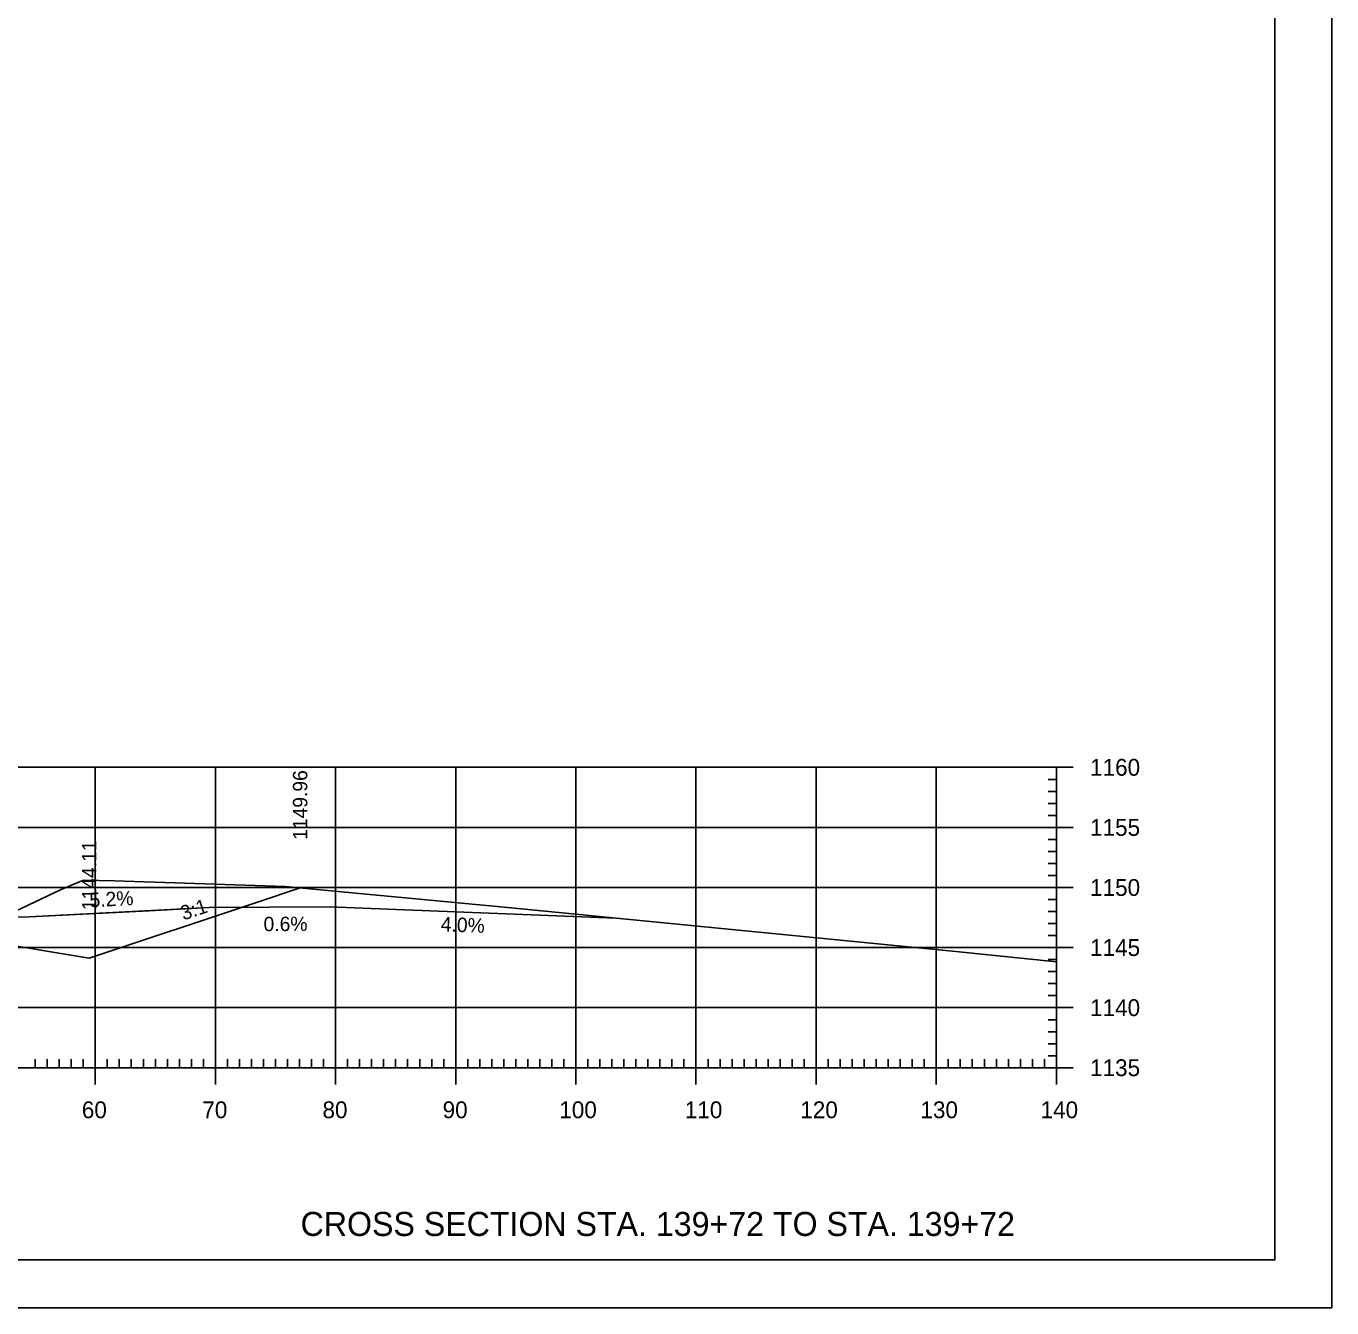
# Model space of a CAD drawing. Extents: x 1322838 to 1324533, y 339903 to 351025.
# Drawn here: x 1324262.2 to 1324370.9, y 342490.3 to 342596.9 of the extents above; entities that cross this region are included whole.
import ezdxf

# ---------------------------------------------------------------- set-up
doc = ezdxf.new("R2010")
doc.units = 0
for name, color, linetype in [('R_Axis', 7, 'Continuous'), ('R_Axis Annot', 7, 'Continuous'), ('R_Border', 7, 'Continuous'), ('R_Draft', 7, 'Continuous'), ('R_Drive', 7, 'Continuous'), ('R_Exist Surface', 7, 'Continuous'), ('R_Fin Surface', 7, 'Continuous'), ('R_Fin Surface Annot', 7, 'Continuous'), ('R_Grid', 7, 'Continuous'), ('R_No Plot', 7, 'Continuous')]:
    doc.layers.add(name, color=color, linetype=linetype)

msp = doc.modelspace()

# ---------------------------------------------------------------- linework, layer by layer
at = {"layer": 'R_Axis'}
for p, q in [((1324349.36, 342535.25), (1324346.56, 342535.25)), ((1324347.96, 342510.25), (1324347.96, 342535.25)), ((1324347.96, 342534.25), (1324347.26, 342534.25)), ((1324347.96, 342533.25), (1324347.26, 342533.25)), ((1324347.96, 342532.25), (1324347.26, 342532.25)), ((1324347.96, 342531.25), (1324347.26, 342531.25)), ((1324349.36, 342530.25), (1324346.56, 342530.25)), ((1324347.96, 342529.25), (1324347.26, 342529.25)), ((1324347.96, 342528.25), (1324347.26, 342528.25)), ((1324347.96, 342527.25), (1324347.26, 342527.25)), ((1324347.96, 342526.25), (1324347.26, 342526.25)), ((1324349.36, 342525.25), (1324346.56, 342525.25)), ((1324347.96, 342524.25), (1324347.26, 342524.25)), ((1324347.96, 342523.25), (1324347.26, 342523.25)), ((1324347.96, 342522.25), (1324347.26, 342522.25)), ((1324347.96, 342521.25), (1324347.26, 342521.25)), ((1324349.36, 342520.25), (1324346.56, 342520.25)), ((1324347.96, 342519.25), (1324347.26, 342519.25)), ((1324347.96, 342518.25), (1324347.26, 342518.25)), ((1324347.96, 342517.25), (1324347.26, 342517.25)), ((1324347.96, 342516.25), (1324347.26, 342516.25)), ((1324349.36, 342515.25), (1324346.56, 342515.25)), ((1324347.96, 342514.25), (1324347.26, 342514.25)), ((1324347.96, 342513.25), (1324347.26, 342513.25)), ((1324267.96, 342508.85), (1324267.96, 342511.65)), ((1324277.96, 342508.85), (1324277.96, 342511.65)), ((1324287.96, 342508.85), (1324287.96, 342511.65)), ((1324297.96, 342508.85), (1324297.96, 342511.65)), ((1324307.96, 342508.85), (1324307.96, 342511.65)), ((1324317.96, 342508.85), (1324317.96, 342511.65)), ((1324327.96, 342508.85), (1324327.96, 342511.65)), ((1324337.96, 342508.85), (1324337.96, 342511.65)), ((1324347.96, 342512.25), (1324347.26, 342512.25)), ((1324347.96, 342508.85), (1324347.96, 342511.65)), ((1324262.96, 342510.25), (1324262.96, 342510.95)), ((1324263.96, 342510.25), (1324263.96, 342510.95)), ((1324264.96, 342510.25), (1324264.96, 342510.95)), ((1324265.96, 342510.25), (1324265.96, 342510.95)), ((1324266.96, 342510.25), (1324266.96, 342510.95)), ((1324268.96, 342510.25), (1324268.96, 342510.95)), ((1324269.96, 342510.25), (1324269.96, 342510.95)), ((1324270.96, 342510.25), (1324270.96, 342510.95)), ((1324271.96, 342510.25), (1324271.96, 342510.95)), ((1324272.96, 342510.25), (1324272.96, 342510.95)), ((1324273.96, 342510.25), (1324273.96, 342510.95)), ((1324274.96, 342510.25), (1324274.96, 342510.95)), ((1324275.96, 342510.25), (1324275.96, 342510.95)), ((1324276.96, 342510.25), (1324276.96, 342510.95)), ((1324278.96, 342510.25), (1324278.96, 342510.95)), ((1324279.96, 342510.25), (1324279.96, 342510.95)), ((1324280.96, 342510.25), (1324280.96, 342510.95)), ((1324281.96, 342510.25), (1324281.96, 342510.95)), ((1324282.96, 342510.25), (1324282.96, 342510.95)), ((1324283.96, 342510.25), (1324283.96, 342510.95)), ((1324284.96, 342510.25), (1324284.96, 342510.95)), ((1324285.96, 342510.25), (1324285.96, 342510.95)), ((1324286.96, 342510.25), (1324286.96, 342510.95)), ((1324288.96, 342510.25), (1324288.96, 342510.95)), ((1324289.96, 342510.25), (1324289.96, 342510.95)), ((1324290.96, 342510.25), (1324290.96, 342510.95)), ((1324291.96, 342510.25), (1324291.96, 342510.95)), ((1324292.96, 342510.25), (1324292.96, 342510.95)), ((1324293.96, 342510.25), (1324293.96, 342510.95)), ((1324294.96, 342510.25), (1324294.96, 342510.95)), ((1324295.96, 342510.25), (1324295.96, 342510.95)), ((1324296.96, 342510.25), (1324296.96, 342510.95)), ((1324298.96, 342510.25), (1324298.96, 342510.95)), ((1324299.96, 342510.25), (1324299.96, 342510.95)), ((1324300.96, 342510.25), (1324300.96, 342510.95)), ((1324301.96, 342510.25), (1324301.96, 342510.95)), ((1324302.96, 342510.25), (1324302.96, 342510.95)), ((1324303.96, 342510.25), (1324303.96, 342510.95)), ((1324304.96, 342510.25), (1324304.96, 342510.95)), ((1324305.96, 342510.25), (1324305.96, 342510.95)), ((1324306.96, 342510.25), (1324306.96, 342510.95)), ((1324308.96, 342510.25), (1324308.96, 342510.95)), ((1324309.96, 342510.25), (1324309.96, 342510.95)), ((1324310.96, 342510.25), (1324310.96, 342510.95)), ((1324311.96, 342510.25), (1324311.96, 342510.95)), ((1324312.96, 342510.25), (1324312.96, 342510.95)), ((1324313.96, 342510.25), (1324313.96, 342510.95)), ((1324314.96, 342510.25), (1324314.96, 342510.95)), ((1324315.96, 342510.25), (1324315.96, 342510.95)), ((1324316.96, 342510.25), (1324316.96, 342510.95)), ((1324318.96, 342510.25), (1324318.96, 342510.95)), ((1324319.96, 342510.25), (1324319.96, 342510.95)), ((1324320.96, 342510.25), (1324320.96, 342510.95)), ((1324321.96, 342510.25), (1324321.96, 342510.95)), ((1324322.96, 342510.25), (1324322.96, 342510.95)), ((1324323.96, 342510.25), (1324323.96, 342510.95)), ((1324324.96, 342510.25), (1324324.96, 342510.95)), ((1324325.96, 342510.25), (1324325.96, 342510.95)), ((1324326.96, 342510.25), (1324326.96, 342510.95)), ((1324328.96, 342510.25), (1324328.96, 342510.95)), ((1324329.96, 342510.25), (1324329.96, 342510.95)), ((1324330.96, 342510.25), (1324330.96, 342510.95)), ((1324331.96, 342510.25), (1324331.96, 342510.95)), ((1324332.96, 342510.25), (1324332.96, 342510.95)), ((1324333.96, 342510.25), (1324333.96, 342510.95)), ((1324334.96, 342510.25), (1324334.96, 342510.95)), ((1324335.96, 342510.25), (1324335.96, 342510.95)), ((1324336.96, 342510.25), (1324336.96, 342510.95)), ((1324338.96, 342510.25), (1324338.96, 342510.95)), ((1324339.96, 342510.25), (1324339.96, 342510.95)), ((1324340.96, 342510.25), (1324340.96, 342510.95)), ((1324341.96, 342510.25), (1324341.96, 342510.95)), ((1324342.96, 342510.25), (1324342.96, 342510.95)), ((1324343.96, 342510.25), (1324343.96, 342510.95)), ((1324344.96, 342510.25), (1324344.96, 342510.95)), ((1324345.96, 342510.25), (1324345.96, 342510.95)), ((1324346.96, 342510.25), (1324346.96, 342510.95)), ((1324347.96, 342511.25), (1324347.26, 342511.25)), ((1324067.96, 342510.25), (1324347.96, 342510.25)), ((1324349.36, 342510.25), (1324346.56, 342510.25))]:
    msp.add_line(p, q, dxfattribs=at)
at = {"layer": 'R_Border'}
for q in [(1324366.14, 342699.71), (1324049.96, 342494.25)]:
    msp.add_line((1324366.14, 342494.25), q, dxfattribs=at)
at = {"layer": 'R_Drive'}
for p, q in [((1324262.45, 342522.8), (1324277.43, 342523.58)), ((1324277.43, 342523.58), (1324287.43, 342523.64)), ((1324287.43, 342523.64), (1324311.26, 342522.69))]:
    msp.add_line(p, q, dxfattribs=at)
for points in [[(1324252.45, 342522.75), (1324262.45, 342522.8), (1324272.44, 342523.32), (1324277.43, 342523.58)], [(1324277.43, 342523.58), (1324287.43, 342523.64)]]:
    msp.add_lwpolyline(points, dxfattribs=at)
at = {"layer": 'R_Exist Surface'}
msp.add_lwpolyline([(1324255.86, 342520.7), (1324265.13, 342525.08), (1324266.98, 342525.87), (1324269.57, 342525.8), (1324283.77, 342525.33), (1324302.57, 342523.57), (1324339.59, 342519.93), (1324347.96, 342519.06)], dxfattribs=at)
at = {"layer": 'R_Fin Surface'}
msp.add_lwpolyline([(1324150.67, 342522.12), (1324159.55, 342523.6), (1324161.74, 342523.97), (1324170.45, 342525.42), (1324171.65, 342525.38), (1324176.45, 342525.23), (1324178.05, 342525.18), (1324178.45, 342525.17), (1324202.05, 342524.44), (1324207.96, 342524.25), (1324231.56, 342523.52), (1324237.46, 342523.33), (1324239.06, 342523.28), (1324239.46, 342523.27), (1324240.65, 342523.22), (1324245.46, 342523.03), (1324252.21, 342521.9), (1324253.92, 342521.62), (1324264.76, 342519.81), (1324267.46, 342519.36), (1324281.47, 342524.03), (1324285.01, 342525.21)], dxfattribs=at)
at = {"layer": 'R_Grid'}
for p, q in [((1324067.96, 342535.25), (1324347.96, 342535.25)), ((1324267.96, 342510.25), (1324267.96, 342535.25)), ((1324277.96, 342510.25), (1324277.96, 342535.25)), ((1324287.96, 342510.25), (1324287.96, 342535.25)), ((1324297.96, 342510.25), (1324297.96, 342535.25)), ((1324307.96, 342510.25), (1324307.96, 342535.25)), ((1324317.96, 342510.25), (1324317.96, 342535.25)), ((1324327.96, 342510.25), (1324327.96, 342535.25)), ((1324337.96, 342510.25), (1324337.96, 342535.25)), ((1324347.96, 342510.25), (1324347.96, 342535.25)), ((1324067.96, 342530.25), (1324347.96, 342530.25)), ((1324067.96, 342525.25), (1324347.96, 342525.25)), ((1324067.96, 342520.25), (1324347.96, 342520.25)), ((1324067.96, 342515.25), (1324347.96, 342515.25)), ((1324067.96, 342510.25), (1324347.96, 342510.25))]:
    msp.add_line(p, q, dxfattribs=at)
at = {"layer": 'R_No Plot'}
msp.add_line((1324037.55, 342490.27), (1324370.89, 342490.27), dxfattribs=at)
for points in [[(1324037.55, 342703.6), (1324370.89, 342703.6), (1324370.89, 342490.27), (1324037.55, 342490.27)], [(1324283.88, 342699.71), (1324303.5, 342699.71), (1324303.5, 342689.83), (1324319.61, 342689.83), (1324342.81, 342689.83), (1324342.93, 342661.67), (1324366.14, 342661.67), (1324366.14, 342494.25), (1324049.96, 342494.25), (1324049.96, 342699.71)]]:
    msp.add_lwpolyline(points, close=True, dxfattribs=at)

# ---------------------------------------------------------------- texts
at = {"layer": 'R_Axis Annot'}
for s, p in [('1160', (1324350.76, 342534.55)), ('1155', (1324350.76, 342529.55)), ('1150', (1324350.76, 342524.55)), ('1145', (1324350.76, 342519.55)), ('1140', (1324350.76, 342514.55)), ('1135', (1324350.76, 342509.55)), ('60', (1324266.84, 342506.05)), ('70', (1324276.87, 342506.05)), ('80', (1324286.87, 342506.05)), ('90', (1324296.87, 342506.05)), ('100', (1324306.58, 342506.05)), ('110', (1324317.03, 342506.05)), ('120', (1324326.64, 342506.05)), ('130', (1324336.64, 342506.05)), ('140', (1324346.64, 342506.05))]:
    msp.add_text(s, height=1.4, dxfattribs=at).set_placement(p)
at = {"layer": 'R_Draft'}
msp.add_text('CROSS SECTION STA. 139+72 TO STA. 139+72', height=2, dxfattribs=at).set_placement((1324285.05, 342496.25))
at = {"layer": 'R_Drive'}
for s, rotation, p in [('5.2% ', 2.9693, (1324267.51, 342523.6)), ('0.6% ', 0.3393, (1324281.97, 342521.61)), ('4.0%', 357.7093, (1324296.7, 342521.61))]:
    msp.add_text(s, height=1.2, rotation=rotation, dxfattribs=at).set_placement(p)
at = {"layer": 'R_Fin Surface Annot'}
for s, rotation, p in [('1149.96', 90, (1324285.61, 342529.21)), ('1144.11', 90, (1324268.06, 342523.36)), ('3:1', 18.4339, (1324275.29, 342522.5))]:
    msp.add_text(s, height=1.2, rotation=rotation, dxfattribs=at).set_placement(p)

doc.saveas('drawing.dxf')
